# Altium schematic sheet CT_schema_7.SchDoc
size 391 x 238 mm
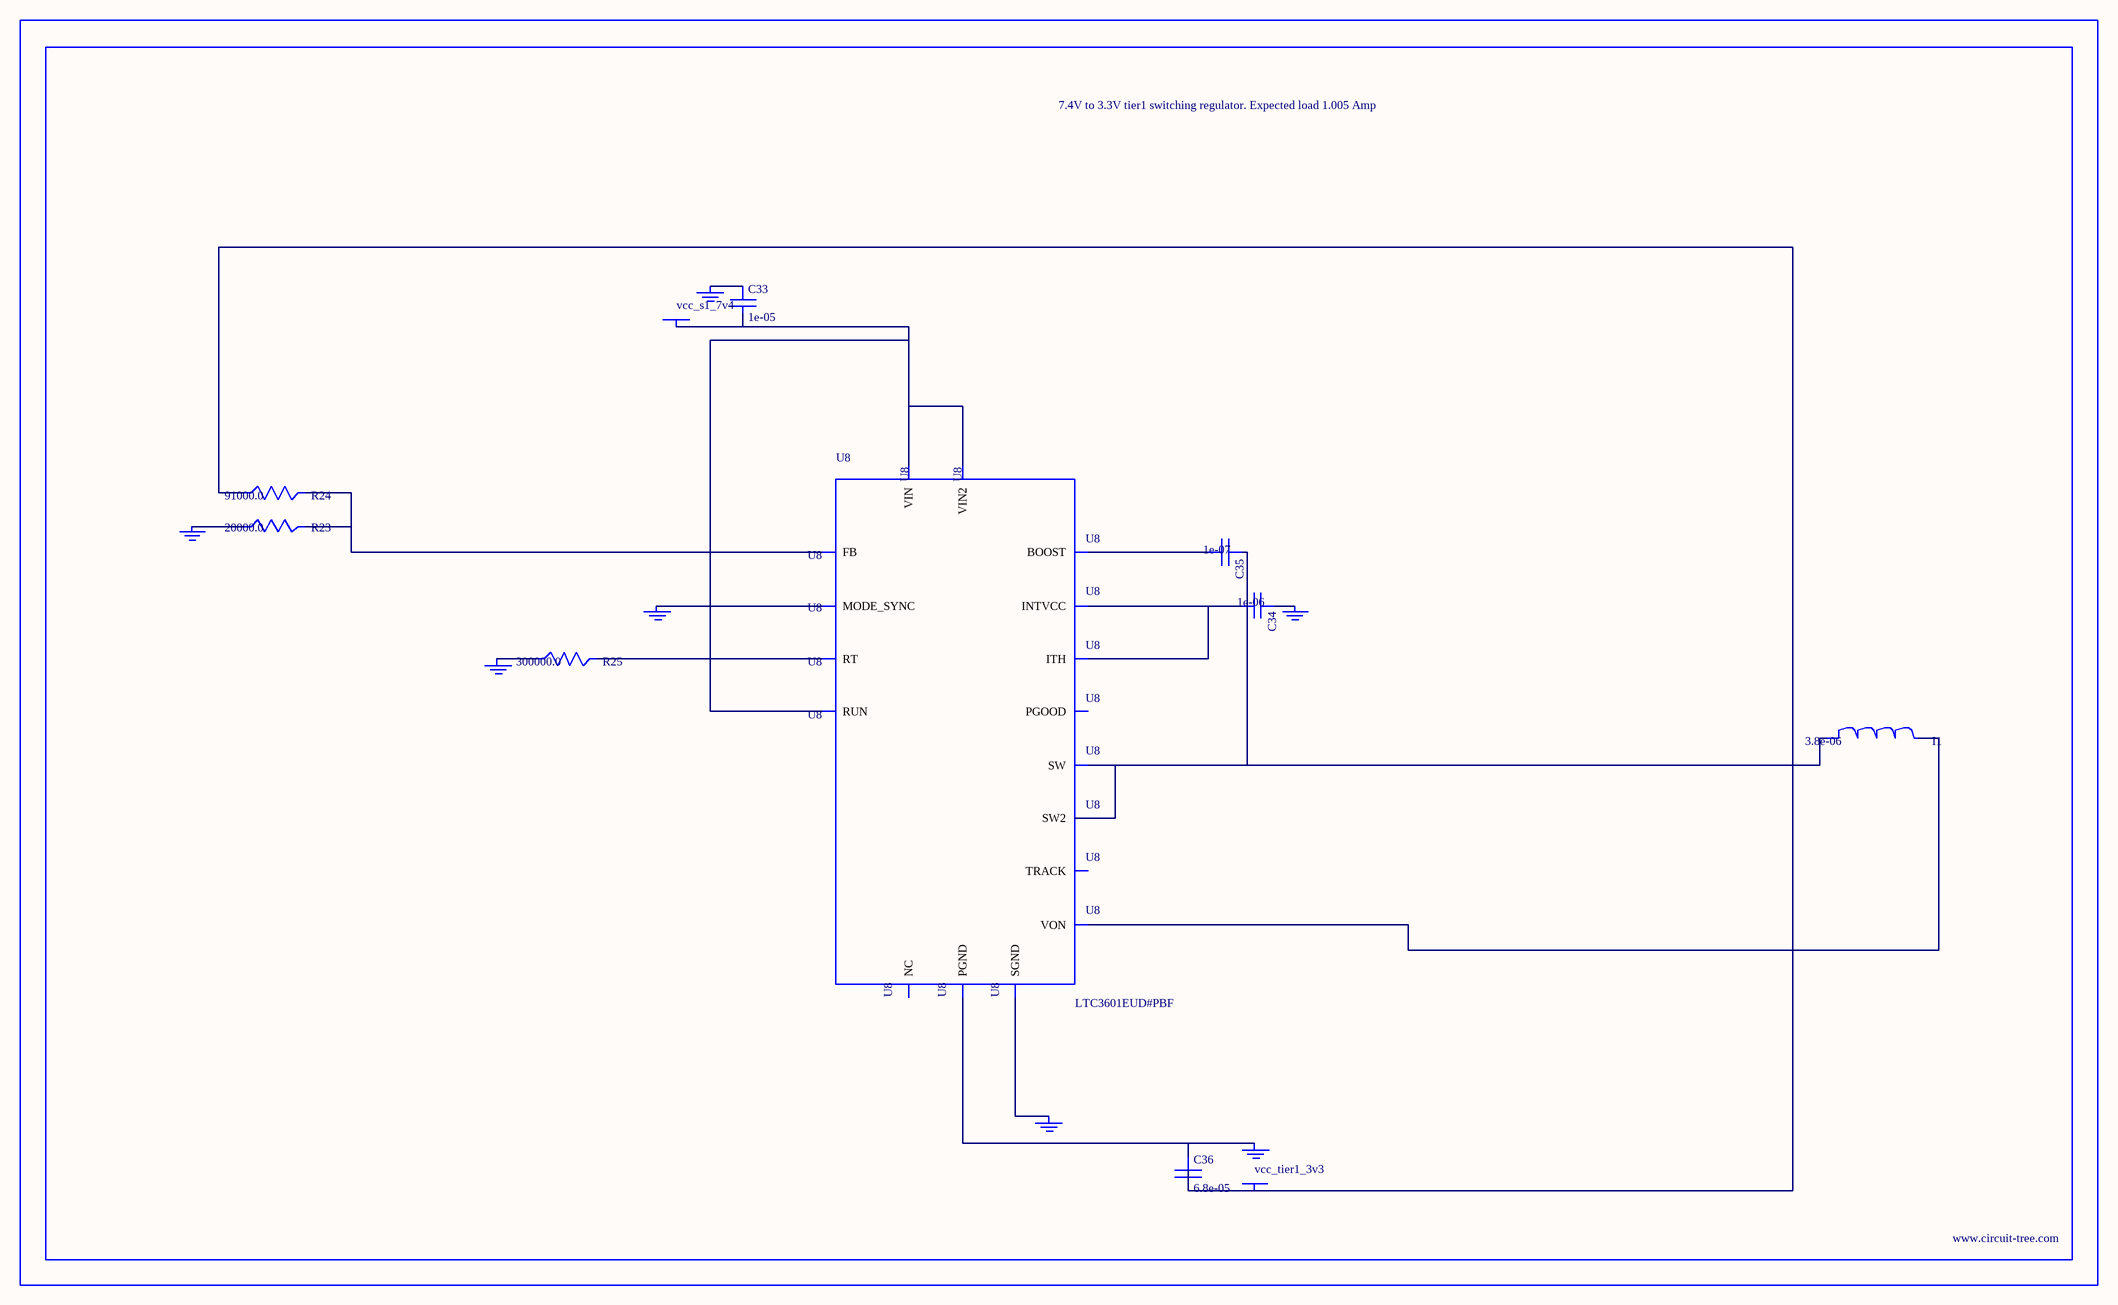
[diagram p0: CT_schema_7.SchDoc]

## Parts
BORDER6  (no value)
C33  1e-05  [C0805]
C34  1e-06  [C0603]
C35  1e-07  [C0402]
C36  6.8e-05  [2220]
GND_INSTANCE_6_0  (no value)
GND_INSTANCE_6_1  (no value)
GND_INSTANCE_6_2  (no value)
GND_INSTANCE_6_3  (no value)
GND_INSTANCE_6_4  (no value)
GND_INSTANCE_6_5  (no value)
GND_INSTANCE_6_6  (no value)
I1  3.8e-06  [DR1040]
POWER_INSTANCE_6_0  vcc_s1_7v4
POWER_INSTANCE_6_1  vcc_tier1_3v3
R23  20000.0  [R0603]
R24  91000.0  [R0603]
R25  300000.0  [R0603]
U8  LTC3601EUD#PBF  [QFN-16_EP]

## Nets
NetC33_1: C33.1 GND_INSTANCE_6_5.0(GND)
NetC33_2: C33.2 POWER_INSTANCE_6_0.0(PWR) U8.14(RUN) U8.15(VIN) U8.16(VIN2)
NetC34_1: C34.1 GND_INSTANCE_6_1.0(GND)
NetC34_2: C34.2 U8.7(INTVCC) U8.12(ITH)
NetC35_1: C35.1 I1.1 U8.3(SW) U8.4(SW2)
NetC35_2: C35.2 U8.6(BOOST)
NetC36_1: C36.1 GND_INSTANCE_6_6.0(GND) U8.17(PGND)
NetC36_2: C36.2 I1.2 POWER_INSTANCE_6_1.0(PWR) R24.1 U8.8(VON)
NetGND_INSTANCE_6_0_0: GND_INSTANCE_6_0.0(GND) U8.1(MODE_SYNC)
NetGND_INSTANCE_6_2_0: GND_INSTANCE_6_2.0(GND) U8.9(SGND)
NetGND_INSTANCE_6_3_0: GND_INSTANCE_6_3.0(GND) R25.1
NetGND_INSTANCE_6_4_0: GND_INSTANCE_6_4.0(GND) R23.1
NetR23_2: R23.2 R24.2 U8.11(FB)
NetR25_2: R25.2 U8.10(RT)

Not connected (* = marked no-connect by the designer): U8 2(PGOOD) 5(NC) 13(TRACK)

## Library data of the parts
BORDER6 = BORDER_PAGE6
C33 = C0805C106K8RACTU
C34 = C0603C105K3RACTU
C35 = C0402C104K3RACTU
C36 = C5750X5R1A686M
GND_INSTANCE_6_0-GND_INSTANCE_6_6 = GND
I1 = DR1040-3R8-R
POWER_INSTANCE_6_0 POWER_INSTANCE_6_1 = PWR
R23 = RC0603JR-0720KL
R24 = RC0603JR-0791KL
R25 = RC0603JR-07300KL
